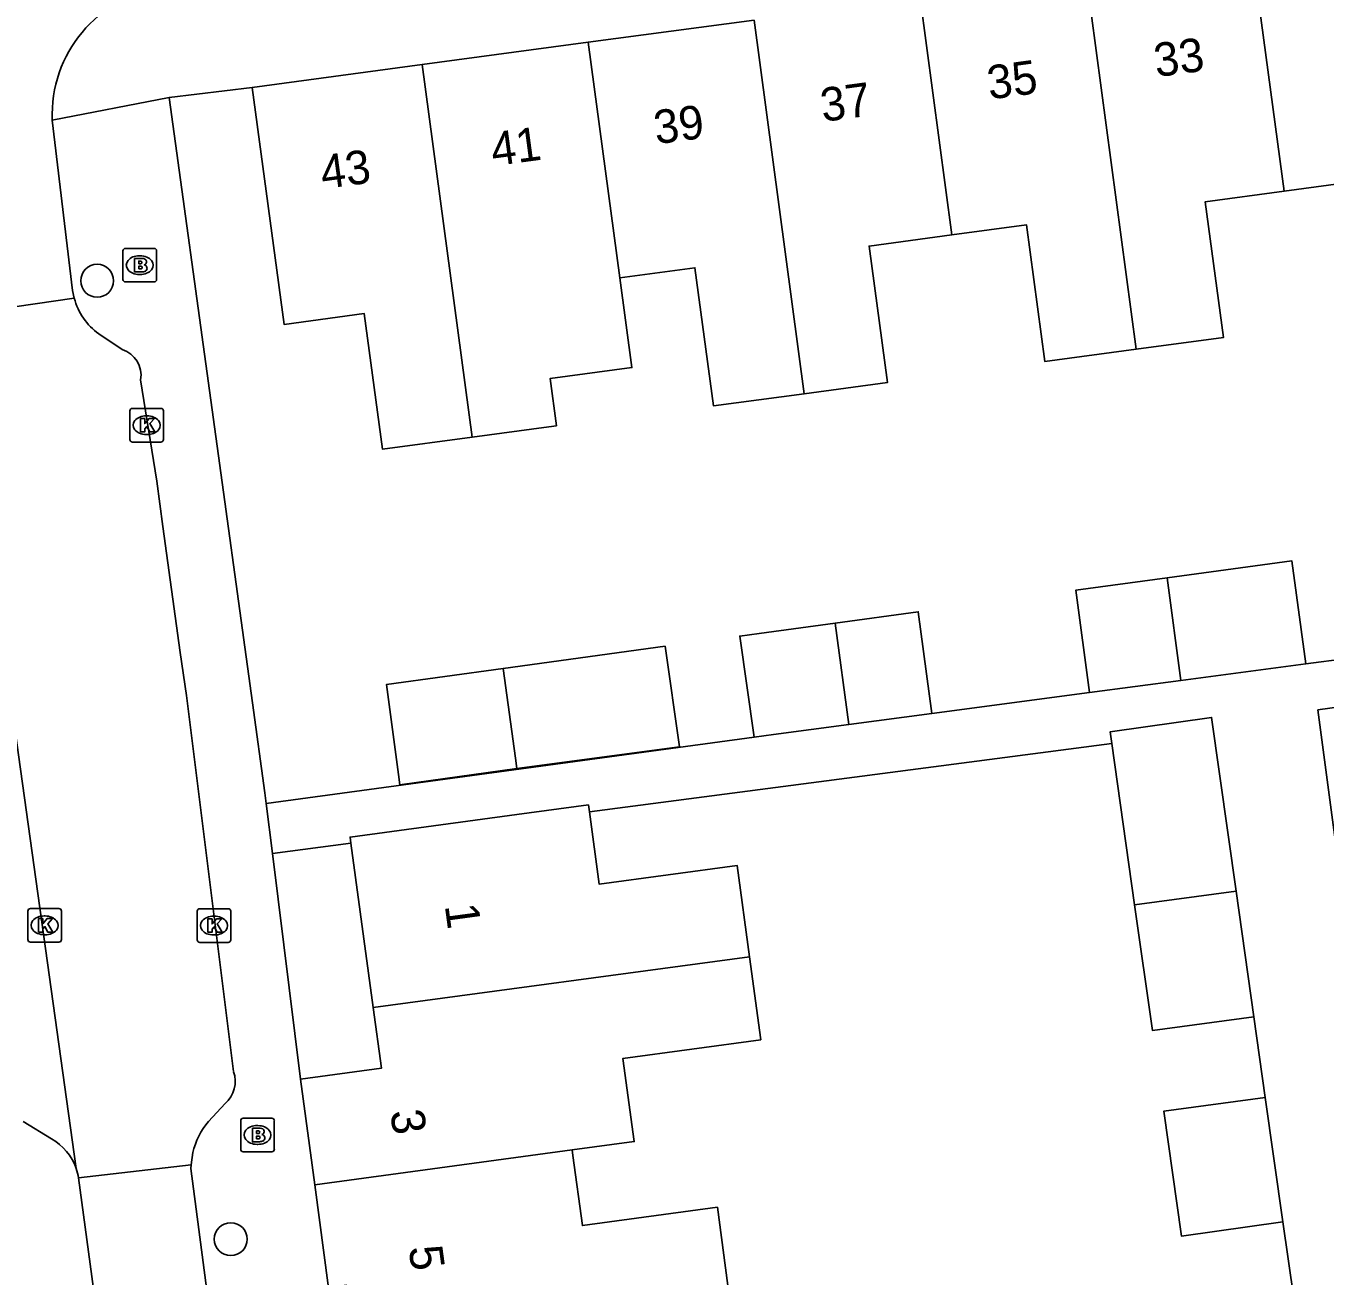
# Model space of a CAD drawing. Extents: x 163150 to 163546, y 380933 to 381635.
# Drawn here: x 163253.82 to 163292.49, y 381438.36 to 381475.58 of the extents above; entities that cross this region are included whole.
import ezdxf

# ---------------------------------------------------------------- set-up
doc = ezdxf.new("R2010")
doc.units = 0
for name, color, linetype in [('IMGEO_Boom', 7, 'Continuous'), ('IMGEO_Brandkraan', 7, 'Continuous'), ('IMGEO_Kolk', 7, 'Continuous'), ('IMGEO_Muur', 7, 'Continuous'), ('IMGEO_Pand', 7, 'Continuous'), ('IMGEO_Pand_nummerreeks', 7, 'Continuous'), ('IMGEO_Rijbaan_lokaal_open', 7, 'Continuous'), ('IMGEO_Voetpad_open', 7, 'Continuous')]:
    doc.layers.add(name, color=color, linetype=linetype)

msp = doc.modelspace()

# ---------------------------------------------------------------- linework, layer by layer
at = {"layer": 'IMGEO_Boom'}
for centre in [(163255.939, 381467.993), (163259.915, 381439.458)]:
    msp.add_circle(centre, 0.489, dxfattribs=at)
at = {"layer": 'IMGEO_Brandkraan'}
for p, q in [((163256.706, 381468.031), (163256.706, 381468.883)), ((163256.781, 381468.957), (163257.633, 381468.957)), ((163257.707, 381468.883), (163257.707, 381468.031)), ((163257.194, 381468.737), (163257.219, 381468.737)), ((163257.217, 381468.177), (163257.192, 381468.177)), ((163257.633, 381467.957), (163256.781, 381467.957)), ((163260.212, 381442.134), (163260.212, 381442.986)), ((163260.287, 381443.06), (163261.139, 381443.06)), ((163261.213, 381442.986), (163261.213, 381442.134)), ((163260.7, 381442.84), (163260.725, 381442.84)), ((163260.723, 381442.28), (163260.698, 381442.28)), ((163261.139, 381442.06), (163260.287, 381442.06))]:
    msp.add_line(p, q, dxfattribs=at)
for points in [[(163256.706, 381468.031), (163256.706, 381468.883)], [(163256.781, 381468.957), (163257.633, 381468.957)], [(163257.707, 381468.883), (163257.707, 381468.031)], [(163257.054, 381468.657), (163257.054, 381468.257), (163257.267, 381468.257)], [(163257.285, 381468.657), (163257.054, 381468.657)], [(163257.233, 381468.576), (163257.179, 381468.576), (163257.179, 381468.5)], [(163257.179, 381468.5), (163257.232, 381468.5)], [(163257.241, 381468.424), (163257.179, 381468.424), (163257.179, 381468.343)], [(163257.179, 381468.343), (163257.241, 381468.343)], [(163257.633, 381467.957), (163256.781, 381467.957)], [(163260.212, 381442.134), (163260.212, 381442.986)], [(163260.287, 381443.06), (163261.139, 381443.06)], [(163261.213, 381442.986), (163261.213, 381442.134)], [(163260.56, 381442.76), (163260.56, 381442.36), (163260.773, 381442.36)], [(163260.791, 381442.76), (163260.56, 381442.76)], [(163260.739, 381442.679), (163260.685, 381442.679), (163260.685, 381442.603)], [(163260.685, 381442.603), (163260.738, 381442.603)], [(163260.747, 381442.527), (163260.685, 381442.527), (163260.685, 381442.446)], [(163260.685, 381442.446), (163260.747, 381442.446)], [(163261.139, 381442.06), (163260.287, 381442.06)]]:
    msp.add_lwpolyline(points, dxfattribs=at)
for centre, radius, start, end in [((163256.783, 381468.881), 0.0765, 91.552, 178.448), ((163256.783, 381468.881), 0.0765, 91.552, 178.448), ((163257.631, 381468.881), 0.0765, 1.552, 88.448), ((163257.631, 381468.881), 0.0765, 1.552, 88.448), ((163257.234, 381468.538), 0.0379, 267.8285, 90.9355), ((163257.289, 381468.512), 0.145, 59.4692, 91.5367), ((163257.314, 381468.559), 0.0922, 285.5137, 58.1501), ((163257.319, 381468.367), 0.105, 301.3115, 78.989), ((163257.242, 381468.383), 0.0404, 269.8759, 90.5077), ((163257.273, 381468.508), 0.251, 268.6676, 293.5347), ((163256.783, 381468.033), 0.0765, 181.552, 268.448), ((163256.783, 381468.033), 0.0765, 181.552, 268.448), ((163257.631, 381468.033), 0.0765, 271.552, 358.448), ((163257.631, 381468.033), 0.0765, 271.552, 358.448), ((163260.289, 381442.984), 0.0765, 91.552, 178.448), ((163260.289, 381442.984), 0.0765, 91.552, 178.448), ((163261.137, 381442.984), 0.0765, 1.552, 88.448), ((163261.137, 381442.984), 0.0765, 1.552, 88.448), ((163260.74, 381442.641), 0.0379, 267.8285, 90.9355), ((163260.795, 381442.615), 0.145, 59.4692, 91.5367), ((163260.82, 381442.662), 0.0922, 285.5137, 58.1501), ((163260.825, 381442.47), 0.105, 301.3115, 78.989), ((163260.748, 381442.486), 0.0404, 269.8759, 90.5077), ((163260.779, 381442.611), 0.251, 268.6676, 293.5347), ((163260.289, 381442.136), 0.0765, 181.552, 268.448), ((163260.289, 381442.136), 0.0765, 181.552, 268.448), ((163261.137, 381442.136), 0.0765, 271.552, 358.448), ((163261.137, 381442.136), 0.0765, 271.552, 358.448)]:
    msp.add_arc(centre, radius, start, end, dxfattribs=at)
for centre, major_axis, ratio, start_param, end_param in [((163257.193, 381468.457), (-0.387, 0.002), 0.722429, 4.712389, 7.853982), ((163257.218, 381468.457), (-0.39, 0.002), 0.717154, 1.570796, 4.712389), ((163260.699, 381442.56), (-0.387, 0.002), 0.722429, 4.712389, 7.853982), ((163260.724, 381442.56), (-0.39, 0.002), 0.717154, 1.570796, 4.712389)]:
    msp.add_ellipse(centre, major_axis=major_axis, ratio=ratio, start_param=start_param, end_param=end_param, dxfattribs=at)
at = {"layer": 'IMGEO_Kolk'}
for p, q in [((163256.912, 381463.265), (163256.912, 381464.117)), ((163256.987, 381464.191), (163257.839, 381464.191)), ((163257.4, 381463.971), (163257.425, 381463.971)), ((163257.913, 381464.117), (163257.913, 381463.265)), ((163257.839, 381463.191), (163256.987, 381463.191)), ((163257.423, 381463.411), (163257.398, 381463.411)), ((163253.875, 381448.375), (163253.875, 381449.227)), ((163253.95, 381449.301), (163254.802, 381449.301)), ((163254.876, 381449.227), (163254.876, 381448.375)), ((163258.916, 381448.368), (163258.916, 381449.22)), ((163258.991, 381449.294), (163259.843, 381449.294)), ((163259.917, 381449.22), (163259.917, 381448.368)), ((163254.363, 381449.081), (163254.388, 381449.081)), ((163259.404, 381449.074), (163259.429, 381449.074)), ((163254.386, 381448.521), (163254.361, 381448.521)), ((163259.427, 381448.514), (163259.402, 381448.514)), ((163254.802, 381448.301), (163253.95, 381448.301)), ((163259.843, 381448.294), (163258.991, 381448.294))]:
    msp.add_line(p, q, dxfattribs=at)
for points in [[(163256.912, 381463.265), (163256.912, 381464.117)], [(163256.987, 381464.191), (163257.839, 381464.191)], [(163257.233, 381463.891), (163257.356, 381463.891), (163257.356, 381463.74), (163257.486, 381463.891), (163257.65, 381463.891), (163257.504, 381463.74), (163257.657, 381463.491), (163257.505, 381463.491), (163257.42, 381463.655), (163257.356, 381463.588), (163257.356, 381463.491), (163257.233, 381463.491), (163257.233, 381463.891)], [(163257.913, 381464.117), (163257.913, 381463.265)], [(163257.839, 381463.191), (163256.987, 381463.191)], [(163253.875, 381448.375), (163253.875, 381449.227)], [(163253.95, 381449.301), (163254.802, 381449.301)], [(163254.876, 381449.227), (163254.876, 381448.375)], [(163258.916, 381448.368), (163258.916, 381449.22)], [(163258.991, 381449.294), (163259.843, 381449.294)], [(163259.917, 381449.22), (163259.917, 381448.368)], [(163254.196, 381449.001), (163254.319, 381449.001), (163254.319, 381448.85), (163254.449, 381449.001), (163254.613, 381449.001), (163254.467, 381448.85), (163254.62, 381448.601), (163254.468, 381448.601), (163254.383, 381448.765), (163254.319, 381448.698), (163254.319, 381448.601), (163254.196, 381448.601), (163254.196, 381449.001)], [(163259.237, 381448.994), (163259.36, 381448.994), (163259.36, 381448.843), (163259.49, 381448.994), (163259.654, 381448.994), (163259.508, 381448.843), (163259.661, 381448.594), (163259.509, 381448.594), (163259.424, 381448.758), (163259.36, 381448.691), (163259.36, 381448.594), (163259.237, 381448.594), (163259.237, 381448.994)], [(163254.802, 381448.301), (163253.95, 381448.301)], [(163259.843, 381448.294), (163258.991, 381448.294)]]:
    msp.add_lwpolyline(points, dxfattribs=at)
for centre, start, end in [((163256.989, 381464.115), 91.552, 178.448), ((163256.989, 381464.115), 91.552, 178.448), ((163257.837, 381464.115), 1.552, 88.448), ((163257.837, 381464.115), 1.552, 88.448), ((163256.989, 381463.267), 181.552, 268.448), ((163256.989, 381463.267), 181.552, 268.448), ((163257.837, 381463.267), 271.552, 358.448), ((163257.837, 381463.267), 271.552, 358.448), ((163253.952, 381449.225), 91.552, 178.448), ((163253.952, 381449.225), 91.552, 178.448), ((163254.8, 381449.225), 1.552, 88.448), ((163254.8, 381449.225), 1.552, 88.448), ((163258.993, 381449.218), 91.552, 178.448), ((163258.993, 381449.218), 91.552, 178.448), ((163259.841, 381449.218), 1.552, 88.448), ((163259.841, 381449.218), 1.552, 88.448), ((163253.952, 381448.377), 181.552, 268.448), ((163253.952, 381448.377), 181.552, 268.448), ((163254.8, 381448.377), 271.552, 358.448), ((163254.8, 381448.377), 271.552, 358.448), ((163258.993, 381448.37), 181.552, 268.448), ((163258.993, 381448.37), 181.552, 268.448), ((163259.841, 381448.37), 271.552, 358.448), ((163259.841, 381448.37), 271.552, 358.448)]:
    msp.add_arc(centre, 0.0765, start, end, dxfattribs=at)
for centre, major_axis, ratio, start_param, end_param in [((163257.399, 381463.691), (-0.387, 0.002), 0.722429, 4.712389, 7.853982), ((163257.424, 381463.691), (-0.39, 0.002), 0.717154, 1.570796, 4.712389), ((163254.362, 381448.801), (-0.387, 0.002), 0.722429, 4.712389, 7.853982), ((163254.387, 381448.801), (-0.39, 0.002), 0.717154, 1.570796, 4.712389), ((163259.403, 381448.794), (-0.387, 0.002), 0.722429, 4.712389, 7.853982), ((163259.428, 381448.794), (-0.39, 0.002), 0.717154, 1.570796, 4.712389)]:
    msp.add_ellipse(centre, major_axis=major_axis, ratio=ratio, start_param=start_param, end_param=end_param, dxfattribs=at)
at = {"layer": 'IMGEO_Muur'}
msp.add_lwpolyline([(163260.561, 381455.423), (163258.081, 381473.453)], dxfattribs=at)
at = {"layer": 'IMGEO_Pand'}
for points in [[(163291.273, 381470.657), (163290.321, 381477.746)], [(163285.379, 381477.082), (163286.874, 381465.952)], [(163281.387, 381469.357), (163280.438, 381476.419)], [(163270.556, 381475.092), (163275.497, 381475.755)], [(163275.497, 381475.755), (163276.991, 381464.627)], [(163265.615, 381474.428), (163270.556, 381475.092)], [(163271.498, 381468.076), (163270.556, 381475.092)], [(163260.555, 381473.749), (163265.615, 381474.428)], [(163265.615, 381474.428), (163267.104, 381463.34)], [(163267.104, 381463.34), (163264.431, 381462.981), (163263.89, 381467.013), (163261.502, 381466.693), (163260.555, 381473.749)], [(163296.756, 381467.285), (163294.094, 381466.927), (163293.552, 381470.963), (163291.273, 381470.657)], [(163286.874, 381465.952), (163289.465, 381466.3), (163288.923, 381470.341), (163291.273, 381470.657)], [(163286.874, 381465.952), (163284.155, 381465.587), (163283.608, 381469.655), (163281.387, 381469.357)], [(163281.387, 381469.357), (163278.919, 381469.025), (163279.465, 381464.959), (163276.991, 381464.627)], [(163271.498, 381468.076), (163271.856, 381465.407), (163269.422, 381465.08), (163269.611, 381463.677), (163269.387, 381463.647), (163267.104, 381463.34)], [(163276.991, 381464.627), (163274.288, 381464.264), (163273.736, 381468.377), (163271.498, 381468.076)], [(163291.917, 381456.584), (163291.505, 381459.651), (163287.788, 381459.145)], [(163287.788, 381459.145), (163285.071, 381458.776), (163285.48, 381455.731)], [(163287.788, 381459.145), (163288.199, 381456.091)], [(163280.788, 381455.109), (163280.381, 381458.138), (163277.907, 381457.801)], [(163277.907, 381457.801), (163275.645, 381457.494), (163275.068, 381457.415), (163275.498, 381454.399)], [(163277.907, 381457.801), (163278.313, 381454.781)], [(163268.43, 381453.468), (163273.274, 381454.113), (163272.846, 381457.113), (163268.029, 381456.45)], [(163288.199, 381456.091), (163291.917, 381456.584)], [(163268.029, 381456.45), (163264.548, 381455.971), (163264.908, 381453.295), (163264.949, 381452.989), (163268.43, 381453.468)], [(163268.029, 381456.45), (163268.389, 381453.774), (163268.43, 381453.468)], [(163285.48, 381455.731), (163288.199, 381456.091)], [(163278.313, 381454.781), (163280.788, 381455.109)], [(163286.148, 381454.214), (163286.098, 381454.566), (163289.116, 381454.992), (163289.846, 381449.822)], [(163275.498, 381454.399), (163276.074, 381454.484), (163278.313, 381454.781)], [(163286.825, 381449.415), (163286.148, 381454.214)], [(163263.492, 381451.248), (163263.467, 381451.43), (163268.437, 381452.102), (163270.562, 381452.389), (163270.591, 381452.177)], [(163270.591, 381452.177), (163270.881, 381450.03), (163274.99, 381450.586), (163275.358, 381447.868)], [(163263.492, 381451.248), (163264.154, 381446.357)], [(163289.846, 381449.822), (163286.825, 381449.415)], [(163289.846, 381449.822), (163290.373, 381446.082)], [(163290.373, 381446.082), (163287.352, 381445.674), (163286.825, 381449.415)], [(163275.358, 381447.868), (163264.154, 381446.357)], [(163275.358, 381447.868), (163275.692, 381445.395), (163271.593, 381444.841), (163271.928, 381442.362), (163270.08, 381442.113)], [(163264.154, 381446.357), (163264.399, 381444.548), (163261.99, 381444.222)], [(163262.415, 381441.079), (163261.99, 381444.222)], [(163290.714, 381443.672), (163287.693, 381443.264), (163288.217, 381439.55), (163291.235, 381439.976)], [(163290.714, 381443.672), (163291.235, 381439.976)], [(163262.415, 381441.079), (163270.08, 381442.113)], [(163270.08, 381442.113), (163270.102, 381441.951), (163270.384, 381439.863), (163274.402, 381440.407), (163274.768, 381437.7)], [(163263.617, 381436.197), (163263.362, 381438.084), (163262.83, 381438.012), (163262.415, 381441.079)]]:
    msp.add_lwpolyline(points, dxfattribs=at)
at = {"layer": 'IMGEO_Rijbaan_lokaal_open'}
for points in [[(163254.604, 381472.77), (163255.209, 381467.701), (163255.257, 381467.47)], [(163255.257, 381467.47), (163251.759, 381466.968)], [(163255.318, 381441.565), (163251.818, 381466.551)], [(163255.99, 381466.411), (163256.68, 381465.942)], [(163257.23, 381465.042), (163257.717, 381462.026), (163257.898, 381460.677), (163258.412, 381456.927), (163258.597, 381455.641), (163260.001, 381444.445)], [(163259.752, 381443.494), (163259.252, 381442.964)], [(163258.787, 381442.035), (163258.739, 381441.673)], [(163255.386, 381441.283), (163255.377, 381441.352), (163255.318, 381441.565)], [(163255.386, 381441.283), (163258.739, 381441.673)], [(163258.739, 381441.673), (163258.724, 381441.564), (163259.331, 381436.948), (163259.382, 381436.565)], [(163256.078, 381436.175), (163256.033, 381436.508), (163255.386, 381441.283)]]:
    msp.add_lwpolyline(points, dxfattribs=at)
for centre, radius, start, end in [((163258.401, 381472.943), 3.801, 97.3209, 182.6036), ((163257.108, 381467.968), 1.917, 195.0648, 234.3143), ((163256.46, 381465.189), 0.784, 349.1828, 73.6764), ((163259.155, 381444.158), 0.893, 311.9521, 18.7032), ((163261.013, 381441.501), 2.29, 140.297, 166.5236)]:
    msp.add_arc(centre, radius, start, end, dxfattribs=at)
at = {"layer": 'IMGEO_Voetpad_open'}
for points in [[(163258.081, 381473.453), (163260.555, 381473.749)], [(163258.081, 381473.453), (163254.604, 381472.77)], [(163260.969, 381452.43), (163260.929, 381452.748), (163260.561, 381455.423), (163258.081, 381473.453)], [(163316.325, 381417.883), (163297.626, 381415.095), (163292.28, 381455.215), (163295.412, 381455.658), (163310.949, 381457.733)], [(163293.141, 381456.746), (163291.917, 381456.584)], [(163285.48, 381455.731), (163280.788, 381455.109)], [(163275.498, 381454.399), (163260.969, 381452.43)], [(163270.591, 381452.177), (163286.148, 381454.214)], [(163261.154, 381450.941), (163260.969, 381452.43)], [(163261.154, 381450.941), (163263.492, 381451.248)], [(163261.99, 381444.222), (163261.154, 381450.941)], [(163290.373, 381446.082), (163290.544, 381444.873), (163290.714, 381443.672)], [(163254.58, 381442.446), (163253.738, 381442.963)], [(163291.235, 381439.976), (163294.836, 381414.98), (163291.731, 381414.576), (163275.971, 381412.525)]]:
    msp.add_lwpolyline(points, dxfattribs=at)
msp.add_arc((163253.78, 381441.026), 1.63, 19.3054, 60.5993, dxfattribs=at)

# ---------------------------------------------------------------- texts
at = {"layer": 'IMGEO_Pand_nummerreeks'}
for s, rotation, p in [('33', 7.6476, (163287.468, 381474.053)), ('35', 7.6476, (163282.505, 381473.386)), ('37', 7.6476, (163277.542, 381472.72)), ('39', 7.6476, (163272.58, 381472.054)), ('41', 7.6476, (163267.729, 381471.402)), ('43', 7.6476, (163262.654, 381470.721)), ('1', 277.7118, (163266.286, 381449.392)), ('3', 277.7061, (163264.663, 381443.261)), ('5', 277.6774, (163265.21, 381439.212))]:
    msp.add_text(s, height=1, rotation=rotation, dxfattribs=at).set_placement(p)

doc.saveas('drawing.dxf')
